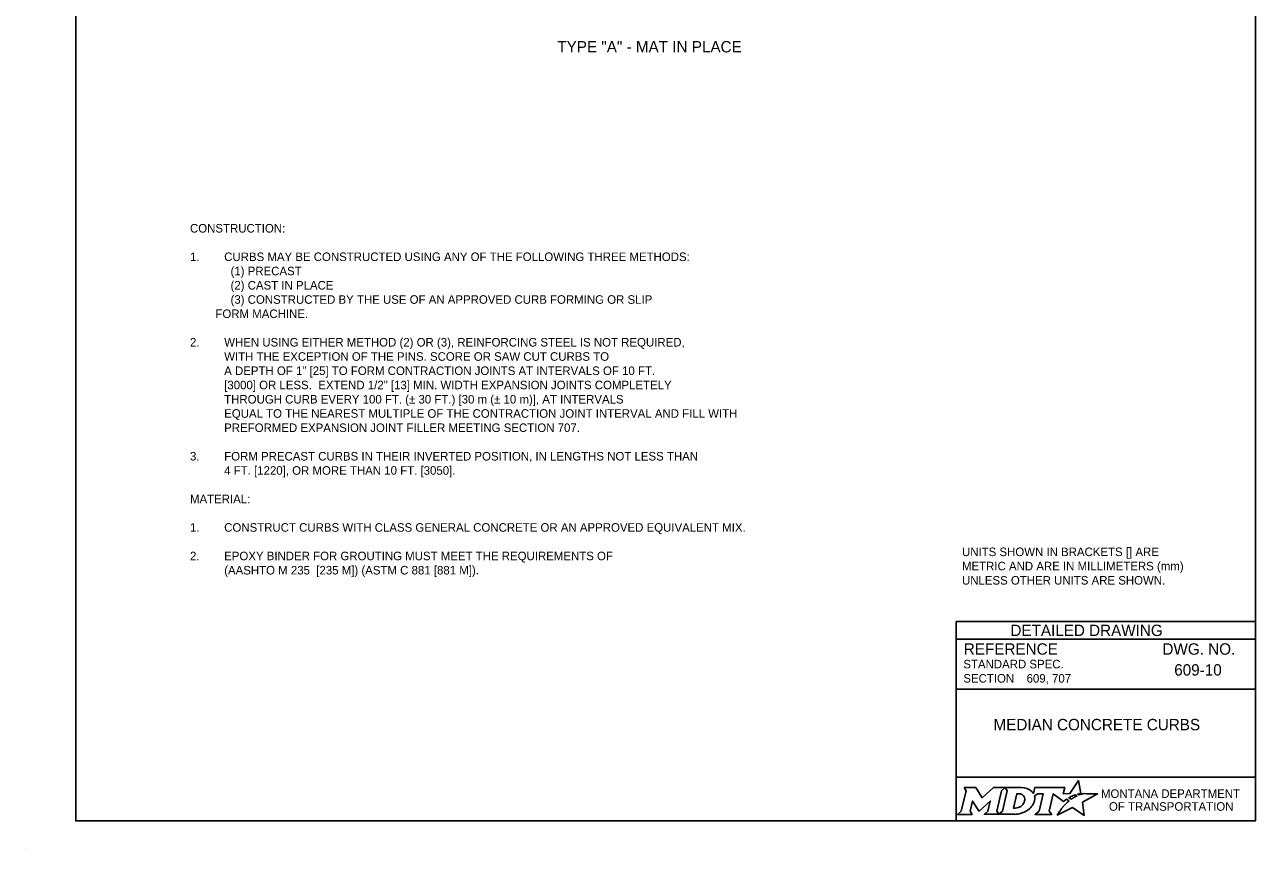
# Model space of a CAD drawing. Extents: x 49991.4 to 50021, y 49987.6 to 50011.4.
# Drawn here: x 49999.98 to 50008.61, y 49999.86 to 50005.65 of the extents above; entities that cross this region are included whole.
import ezdxf

# ---------------------------------------------------------------- set-up
doc = ezdxf.new("R2010")
doc.units = 0
doc.layers.add('Level 1', color=7, linetype='Continuous')
doc.layers.add('Level 2', color=7, linetype='Continuous')

msp = doc.modelspace()

# ---------------------------------------------------------------- linework, layer by layer
at = {"layer": 'Level 1'}
msp.add_line((49999.9766, 49999.8624), (49999.9766, 49999.8624), dxfattribs=at)
msp.add_lwpolyline([(50008.6146, 50011.2628), (50000.3356, 50011.2628), (50000.3356, 50000.0624), (50008.6146, 50000.0624)], close=True, dxfattribs=at)
at = {"layer": 'Level 2'}
for p, q in [((50008.6146, 50001.4624), (50006.5146, 50001.4624)), ((50006.5146, 50001.4624), (50006.5146, 50000.0624)), ((50008.6146, 50001.3374), (50006.5146, 50001.3374)), ((50008.2507, 50001.1223), (50008.2507, 50001.1223)), ((50008.6146, 50000.9874), (50006.5146, 50000.9874)), ((50007.0089, 50001.0629), (50007.0089, 50001.0629)), ((50007.5646, 50000.7383), (50007.5646, 50000.7383)), ((50008.6146, 50000.3693), (50006.5146, 50000.3693))]:
    msp.add_line(p, q, dxfattribs=at)
for points in [[(50006.5701, 50000.2974), (50006.5842, 50000.274), (50006.5507, 50000.1307), (50006.525, 50000.1082), (50006.6266, 50000.1082), (50006.6131, 50000.131), (50006.6293, 50000.2011), (50006.673, 50000.1321), (50006.6783, 50000.1321), (50006.7534, 50000.2016), (50006.737, 50000.1305), (50006.7123, 50000.1085), (50006.8139, 50000.1085), (50006.8001, 50000.1318), (50006.8333, 50000.2742)], [(50006.8333, 50000.2742), (50006.8586, 50000.2974), (50006.7762, 50000.2974), (50006.6966, 50000.2244), (50006.6521, 50000.2971), (50006.5701, 50000.2974)], [(50006.9722, 50000.2974), (50006.8586, 50000.2974), (50006.8733, 50000.2745), (50006.8394, 50000.1307), (50006.8139, 50000.1085), (50006.9245, 50000.1085)], [(50007.3771, 50000.2447), (50007.3668, 50000.2503), (50007.3784, 50000.2531), (50007.39, 50000.2551), (50007.3726, 50000.3452), (50007.3131, 50000.2539), (50007.2658, 50000.2532), (50007.2761, 50000.2973), (50007.0669, 50000.2974), (50007.0568, 50000.2549), (50007.051, 50000.2632)], [(50006.9962, 50000.2107), (50006.995, 50000.2026), (50006.9918, 50000.1933), (50006.9876, 50000.1851), (50006.982, 50000.1776), (50006.9755, 50000.1707), (50006.9676, 50000.1644), (50006.9593, 50000.1597), (50006.9502, 50000.1558), (50006.9411, 50000.1535), (50006.9319, 50000.1526), (50006.916, 50000.1526), (50006.9396, 50000.2526), (50006.9556, 50000.2526), (50006.9632, 50000.252), (50006.9708, 50000.2501), (50006.9774, 50000.2471), (50006.9835, 50000.2429), (50006.9883, 50000.2379), (50006.992, 50000.2319), (50006.9947, 50000.2257), (50006.9963, 50000.2183), (50006.9963, 50000.2153), (50006.9962, 50000.2107)], [(50007.0636, 50000.2383), (50007.0882, 50000.2514), (50007.1251, 50000.2514), (50007.0965, 50000.1309), (50007.069, 50000.1082), (50007.1852, 50000.1082), (50007.1682, 50000.1311), (50007.1964, 50000.2513), (50007.2677, 50000.1996), (50007.2888, 50000.2147), (50007.3085, 50000.2038)], [(50007.2527, 50000.1479), (50007.2374, 50000.1235), (50007.2327, 50000.116), (50007.2269, 50000.1074), (50007.2246, 50000.1031), (50007.3299, 50000.1562), (50007.4138, 50000.1011), (50007.4007, 50000.1938), (50007.5076, 50000.2522), (50007.4583, 50000.253), (50007.4282, 50000.2534), (50007.4074, 50000.2537), (50007.4006, 50000.2522), (50007.3957, 50000.251), (50007.3873, 50000.2487), (50007.3771, 50000.2447)], [(50007.3267, 50000.2171), (50007.3243, 50000.2154), (50007.306, 50000.225), (50007.3163, 50000.2307), (50007.3204, 50000.2329), (50007.329, 50000.2369), (50007.3347, 50000.2395), (50007.3426, 50000.2425), (50007.3499, 50000.2452), (50007.3617, 50000.2378), (50007.3577, 50000.2357), (50007.3531, 50000.2332), (50007.3489, 50000.231), (50007.3439, 50000.2281), (50007.342, 50000.227), (50007.3393, 50000.2254), (50007.3368, 50000.224), (50007.3345, 50000.2224), (50007.3319, 50000.2206), (50007.3292, 50000.2188), (50007.3267, 50000.2171)], [(50006.9702, 50000.1158), (50006.9786, 50000.1184), (50006.9916, 50000.1238), (50007.012, 50000.1348)], [(50007.2666, 50000.164), (50007.2666, 50000.164)]]:
    msp.add_lwpolyline(points, dxfattribs=at)
for centre, radius, start, end in [((50006.9953, 50000.219), 0.0709, 339.53292, 15.85821), ((50006.9513, 50000.2363), 0.1183, 300.91025, 339.13831)]:
    msp.add_arc(centre, radius, start, end, dxfattribs=at)
for centre, major_axis, ratio, start_param, end_param in [((50006.9701, 50000.25), (0.0834, -0.0037), 0.568097, 0.61298, 1.570796), ((50007.0257, 50000.2573), (0.0361, -0.0295), 0.469099, 1.225588, 1.570796), ((50007.2974, 50000.1941), (-0.0112, -0.0097), 0.021651, 3.157348, 6.283185), ((50006.9248, 50000.2568), (0, 0.1484), 0.987302, 3.139398, 3.456847), ((50007.2597, 50000.1559), (-0.00694, -0.00806), 0.008222, 0, 3.137361), ((50007.2764, 50000.1742), (-0.0098, -0.0102), 0.016458, 3.141593, 6.279097)]:
    msp.add_ellipse(centre, major_axis=major_axis, ratio=ratio, start_param=start_param, end_param=end_param, dxfattribs=at)

# ---------------------------------------------------------------- texts
for s, height, p in [('TYPE "A" - MAT IN PLACE', 0.08, (50003.7152, 50005.4565)), ('CONSTRUCTION:', 0.06, (50001.1373, 50004.1921)), ('1.', 0.06, (50001.1373, 50003.9921)), ('CURBS MAY BE CONSTRUCTED USING ANY OF THE FOLLOWING THREE METHODS:', 0.06, (50001.3773, 50003.9921)), ('  (1) PRECAST', 0.06, (50001.3773, 50003.8921)), ('  (2) CAST IN PLACE', 0.06, (50001.3773, 50003.7921)), ('  (3) CONSTRUCTED BY THE USE OF AN APPROVED CURB FORMING OR SLIP', 0.06, (50001.3773, 50003.6921)), ('        FORM MACHINE.', 0.06, (50001.1373, 50003.5921)), ('2.', 0.06, (50001.1373, 50003.3921)), ('WHEN USING EITHER METHOD (2) OR (3), REINFORCING STEEL IS NOT REQUIRED,', 0.06, (50001.3773, 50003.3921)), ('WITH THE EXCEPTION OF THE PINS. SCORE OR SAW CUT CURBS TO', 0.06, (50001.3773, 50003.2921)), ('A DEPTH OF 1" [25] TO FORM CONTRACTION JOINTS AT INTERVALS OF 10 FT.', 0.06, (50001.3773, 50003.1921)), ('[3000] OR LESS.  EXTEND 1/2" [13] MIN. WIDTH EXPANSION JOINTS COMPLETELY', 0.06, (50001.3773, 50003.0921)), ('THROUGH CURB EVERY 100 FT. (± 30 FT.) [30 m (± 10 m)], AT INTERVALS ', 0.06, (50001.3773, 50002.9921)), ('EQUAL TO THE NEAREST MULTIPLE OF THE CONTRACTION JOINT INTERVAL AND FILL WITH ', 0.06, (50001.3773, 50002.8921)), ('PREFORMED EXPANSION JOINT FILLER MEETING SECTION 707.', 0.06, (50001.3773, 50002.7921)), ('3.', 0.06, (50001.1373, 50002.5921)), ('FORM PRECAST CURBS IN THEIR INVERTED POSITION, IN LENGTHS NOT LESS THAN', 0.06, (50001.3773, 50002.5921)), ('4 FT. [1220], OR MORE THAN 10 FT. [3050].', 0.06, (50001.3773, 50002.4921)), ('MATERIAL:', 0.06, (50001.1373, 50002.2921)), ('1.', 0.06, (50001.1373, 50002.0921)), ('CONSTRUCT CURBS WITH CLASS GENERAL CONCRETE OR AN APPROVED EQUIVALENT MIX.', 0.06, (50001.3773, 50002.0921)), ('2.', 0.06, (50001.1373, 50001.8921)), ('EPOXY BINDER FOR GROUTING MUST MEET THE REQUIREMENTS OF ', 0.06, (50001.3773, 50001.8921)), ('UNITS SHOWN IN BRACKETS [] ARE ', 0.06, (50006.5554, 50001.921)), ('(AASHTO M 235  [235 M]) (ASTM C 881 [881 M]).', 0.06, (50001.3773, 50001.7921)), ('METRIC AND ARE IN MILLIMETERS (mm) ', 0.06, (50006.5554, 50001.821)), ('UNLESS OTHER UNITS ARE SHOWN.', 0.06, (50006.5554, 50001.721)), ('DETAILED DRAWING', 0.0799, (50006.8956, 50001.3599)), ('REFERENCE', 0.08, (50006.5682, 50001.229)), ('DWG. NO.', 0.08, (50007.9624, 50001.229)), ('STANDARD SPEC.', 0.06, (50006.5649, 50001.133)), ('609-10', 0.08, (50008.0451, 50001.0823)), ('SECTION', 0.06, (50006.5649, 50001.033)), ('609, 707', 0.06, (50007.0089, 50001.0329)), ('MEDIAN CONCRETE CURBS', 0.08, (50006.7766, 50000.6983)), ('MONTANA DEPARTMENT', 0.06, (50007.5308, 50000.2236)), ('OF TRANSPORTATION', 0.06, (50007.587, 50000.1336))]:
    msp.add_text(s, height=height, dxfattribs=at).set_placement(p)

doc.saveas('drawing.dxf')
